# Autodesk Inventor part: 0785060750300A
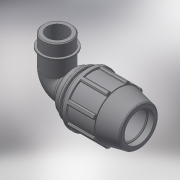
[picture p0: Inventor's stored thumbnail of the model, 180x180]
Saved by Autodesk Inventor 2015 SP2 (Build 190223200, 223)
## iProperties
Created: 2017-02
Part Number: 0785060750300A
Material: Generic
Description: PLASSON 90° ELBOW MALE ADAPTOR 75-3"
Document SubType Name: Modeling
Designer: KIM
Mass: 1366.09 g
Surface Area: 1816.46 cm^2
Volume: 1366.09 cm^3
Density: 1 g/cm^3
Appearance: Default
Author: KIM
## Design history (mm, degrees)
derived "87850.ipt"
feature "Solid1::87850.ipt"
tag "TaggingFeature1"
body "Solid1"
other parameters: "d2" = 75, "d4" = 16.83333, "d5" = 50.5, "d7" = 134, "d9" = 28.85714, "d11" = 6.73333, "d13" = 120 deg, "d14" = 97.5, "d15" = 12 deg, "d16" = 116.58, "d18" = 3.75, "d19" = 35 deg, "d20" = 17.5 deg, "d21" = 124.62, "d23" = 0, "d25" = 360 deg, "d27" = 2.68, "d33" = 1.5, "d42" = 74.74, "d43" = 4.02, "d46" = 2.25, "d51" = 202, "d68" = 13.46667, "d73" = 87.884, "d74" = 33, "d75" = 101.0666, "d76" = 61.5188, "d77" = 36.3, "d79" = 35.1536, "d80" = 2.63652, "d83" = 0, "d84" = 0, "d91" = 100.5, "d93" = 132, "d94" = 87.884, "d95" = 61.5188, "d96" = 13.46667, "d97" = 50 deg, "d98" = 3.36667, "d99" = 113.0826, "d100" = 3.36667, "d101" = 3.36667, "d102" = 8.93333, "d103" = 0, "d_" = 75, "E_" = 134, "A_" = 202, "l_" = 132, "l_2" = 33, "G_" = 87.884
